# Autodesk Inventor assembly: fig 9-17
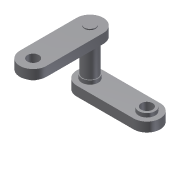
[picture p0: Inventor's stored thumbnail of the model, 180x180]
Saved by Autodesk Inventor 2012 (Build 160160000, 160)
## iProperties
Shininess: 64.0
Length Units: 11269
Angle Units: 11279
Time Units: 11290
Mass Units: 11283
Length Display Precision: 3
Angle Display Precision: 2
Created: 2002-01
Part Number: fig 9-17
Document SubType Name: Assembly
Designer: ***
Density: 0.0
Volumn: 0.0
Area: 0.0
PropertySet Name: Model Information
Control State: 0
Master: False
Checked Out: False
Author: ***
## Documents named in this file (3)
- C:\Users\CadCim\Documents\SAILESH\inventor-2011-fact-prt\c09_inv_2011-prt\c09_inv_2012_prt\fig 9-17.iam
- C:\Users\CadCim\Documents\SAILESH\inventor-2011-fact-prt\c09_inv_2011-prt\c09_inv_2012_prt\Part5.ipt
- C:\Users\CadCim\Documents\SAILESH\inventor-2011-fact-prt\c09_inv_2011-prt\c09_inv_2012_prt\Part6.ipt
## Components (3 placed, 2 different names)
1. Part5:1 — Insert:1
2. Part6:1 — Insert:1, Insert:2
3. Part5:2 — Insert:2
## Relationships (2: Insert 2)
- Insert:1: Part5:1 ↔ Part6:1
- Insert:2: Part6:1 ↔ Part5:2
